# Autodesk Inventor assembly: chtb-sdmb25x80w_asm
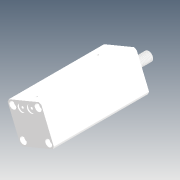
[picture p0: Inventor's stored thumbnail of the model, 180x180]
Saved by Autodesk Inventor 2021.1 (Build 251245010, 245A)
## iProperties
Company: Microsoft
Created: 2018-05
Part Number: chtb-sdmb25x80w_asm
Description: STEP AP214
Document SubType Name: Assembly
Designer: user
Title: chtb-sdmb25x80w_asm.STEP
Author: Windows
Revision Number: ÈÎºÎ
Sending System: SolidWorks 2015
Preprocessor: SwSTEP 2.0
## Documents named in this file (4)
- D:\Vault_2016\Projekty\Clamptek\Hydraulic\CHTB\CHTB-25\Inventor\chtb-sdmb25x80w\chtb-sdmb25x80w_asm.iam
- D:\Vault_2016\Projekty\Clamptek\Hydraulic\CHTB\CHTB-25\Inventor\chtb-sdmb25x80w\CHTB-25QG.ipt
- D:\Vault_2016\Projekty\Clamptek\Hydraulic\CHTB\CHTB-25\Inventor\chtb-sdmb25x80w\CHTB-SDMB25X80NBT.ipt
- D:\Vault_2016\Projekty\Clamptek\Hydraulic\CHTB\CHTB-25\Inventor\chtb-sdmb25x80w\CHTB-SDMB25X80WHSG.ipt
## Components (3 placed, 3 different names)
1. CHTB-25QG_1
2. CHTB-SDMB25X80NBT_2
3. CHTB-SDMB25X80WHSG_3
